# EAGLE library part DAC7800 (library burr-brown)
Dual Monolithic CMOS 12-Bit DAC Multiplying
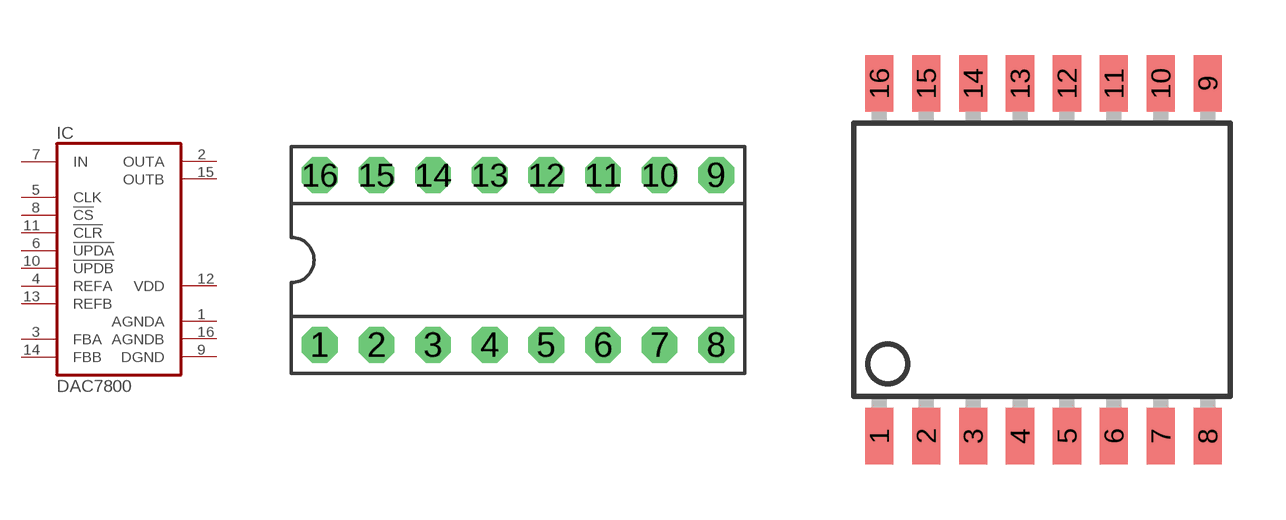
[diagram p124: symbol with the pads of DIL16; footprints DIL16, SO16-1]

Designator prefix IC

## DAC7800P (MPN: DAC7800LPG4; OC_FARNELL: 1509905; OC_NEWARK: 99K1851)  [DIL16]
1  AGNDA  pwr
2  OUTA  out
3  FBA  pas
4  REFA  in
5  CLK  in
6  !UPDA  in
7  IN  in
8  !CS  in
9  DGND  pwr
10  !UPDB  in
11  !CLR  in
12  VDD  pwr
13  REFB  in
14  FBB  pas
15  OUTB  out
16  AGNDB  pwr

## DAC7800U (MPN: DAC7800KU; OC_FARNELL: 1460233; OC_NEWARK: 61M5746)  [SO16-1]
Pads as for DIL16

## Footprint DIL16 (pad centres in mm)
Dual In Line
drill 0.813 pad 1.6 octagon: 1 -8.89,-3.81; 2 -6.35,-3.81; 3 -3.81,-3.81; 4 -1.27,-3.81; 5 1.27,-3.81; 6 3.81,-3.81; 7 6.35,-3.81; 8 8.89,-3.81; 9 8.89,3.81; 10 6.35,3.81; 11 3.81,3.81; 12 1.27,3.81; 13 -1.27,3.81; 14 -3.81,3.81; 15 -6.35,3.81; 16 -8.89,3.81

## Footprint SO16-1 (pad centres in mm)
Small Outline Package
smd 0.762 x 1.524: 1 -4.445,-4.775; 2 -3.175,-4.775; 3 -1.905,-4.775; 4 -0.635,-4.775; 5 0.635,-4.775; 6 1.905,-4.775; 7 3.175,-4.775; 8 4.445,-4.775; 9 4.445,4.775; 10 3.175,4.775; 11 1.905,4.775; 12 0.635,4.775; 13 -0.635,4.775; 14 -1.905,4.775; 15 -3.175,4.775; 16 -4.445,4.775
